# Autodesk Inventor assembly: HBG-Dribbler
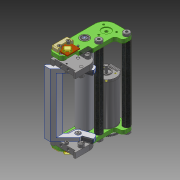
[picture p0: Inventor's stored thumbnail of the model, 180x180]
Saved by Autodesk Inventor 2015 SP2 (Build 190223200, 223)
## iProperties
Created: 2013-07
Part Number: HBG-Dribbler
Document SubType Name: Assembly
Designer: rYan
Mass: 190.705 g
Surface Area: 346.539 cm^2
Volume: 44.227 cm^3
Density: 4.31197 g/cm^3
Author: rYan
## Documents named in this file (3)
- D:\TIGERs GIT\Hardware\mechanik\2016\Inventor\Dribbling Device\HBG-Dribbler.iam
- D:\TIGERs GIT\Hardware\mechanik\2016\Inventor\Dribbling Device\UBG-Dribblerlagerbock.iam
- D:\TIGERs GIT\Hardware\mechanik\2016\Inventor\Dribbling Device\UBG-Dribbling Device.iam
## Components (2 placed, 2 different names)
1. UBG-Dribblerlagerbock:1 [sub-assembly] — Passend:3, Passend:4, Winkel:1
2. UBG-Dribbling Device:1 [sub-assembly] — Passend:3, Passend:4, Winkel:1
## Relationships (3: Mate 2, Angle 1)
- Passend:3 [Mate]: UBG-Dribblerlagerbock:1 ↔ UBG-Dribbling Device:1
- Passend:4 [Mate]: UBG-Dribblerlagerbock:1 ↔ UBG-Dribbling Device:1
- Winkel:1 [Angle]: UBG-Dribblerlagerbock:1 ↔ UBG-Dribbling Device:1
